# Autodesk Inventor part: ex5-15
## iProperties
Created: 2006-03
Part Number: ex5-15
Document SubType Name: Modeling
Designer: Elise Moss
Author: Elise Moss
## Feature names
1. Loft1
2. Shell1
3. Extrusion1
4. Sweep1
5. FaceDraft1
6. Fillet1
7. Fillet2
